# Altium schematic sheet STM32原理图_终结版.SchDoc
size 762 x 508 mm; SheetNumber: 0; SheetTotal: 0
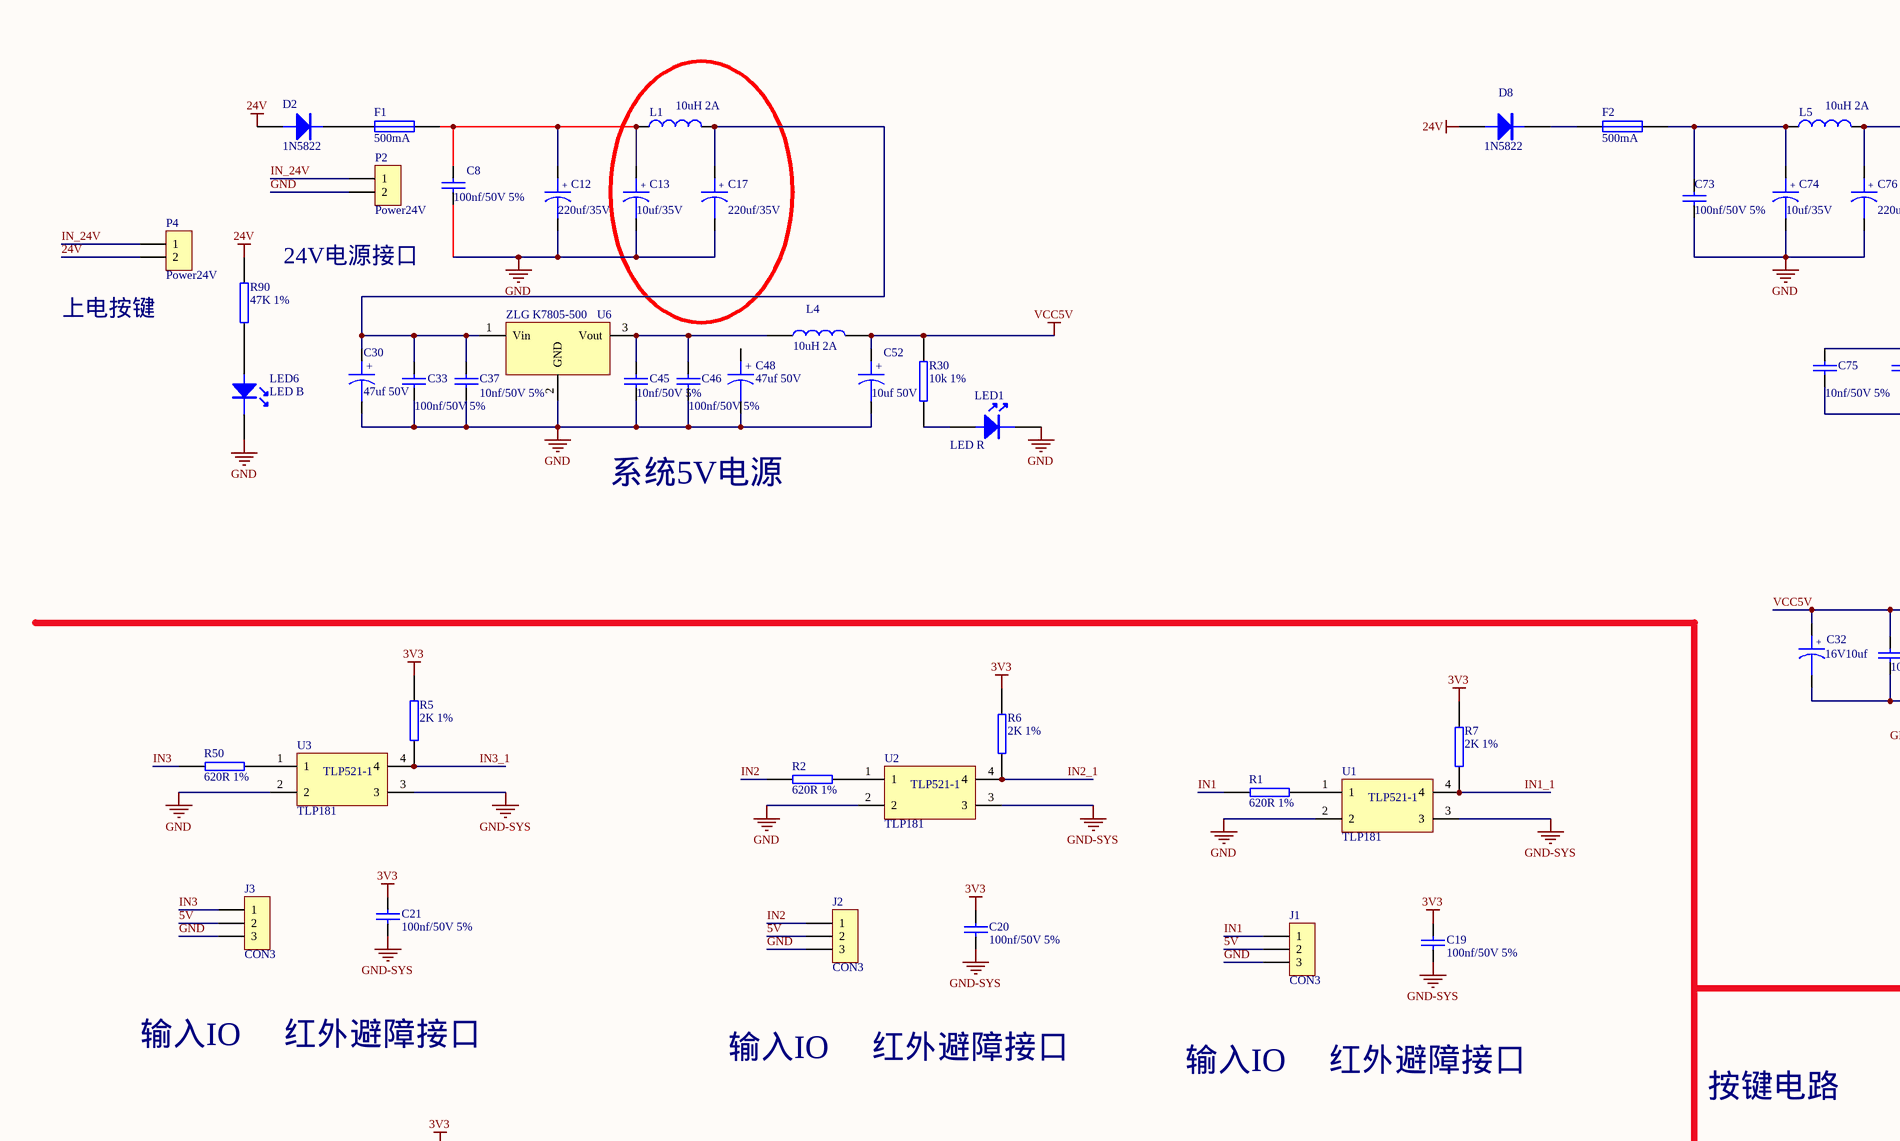
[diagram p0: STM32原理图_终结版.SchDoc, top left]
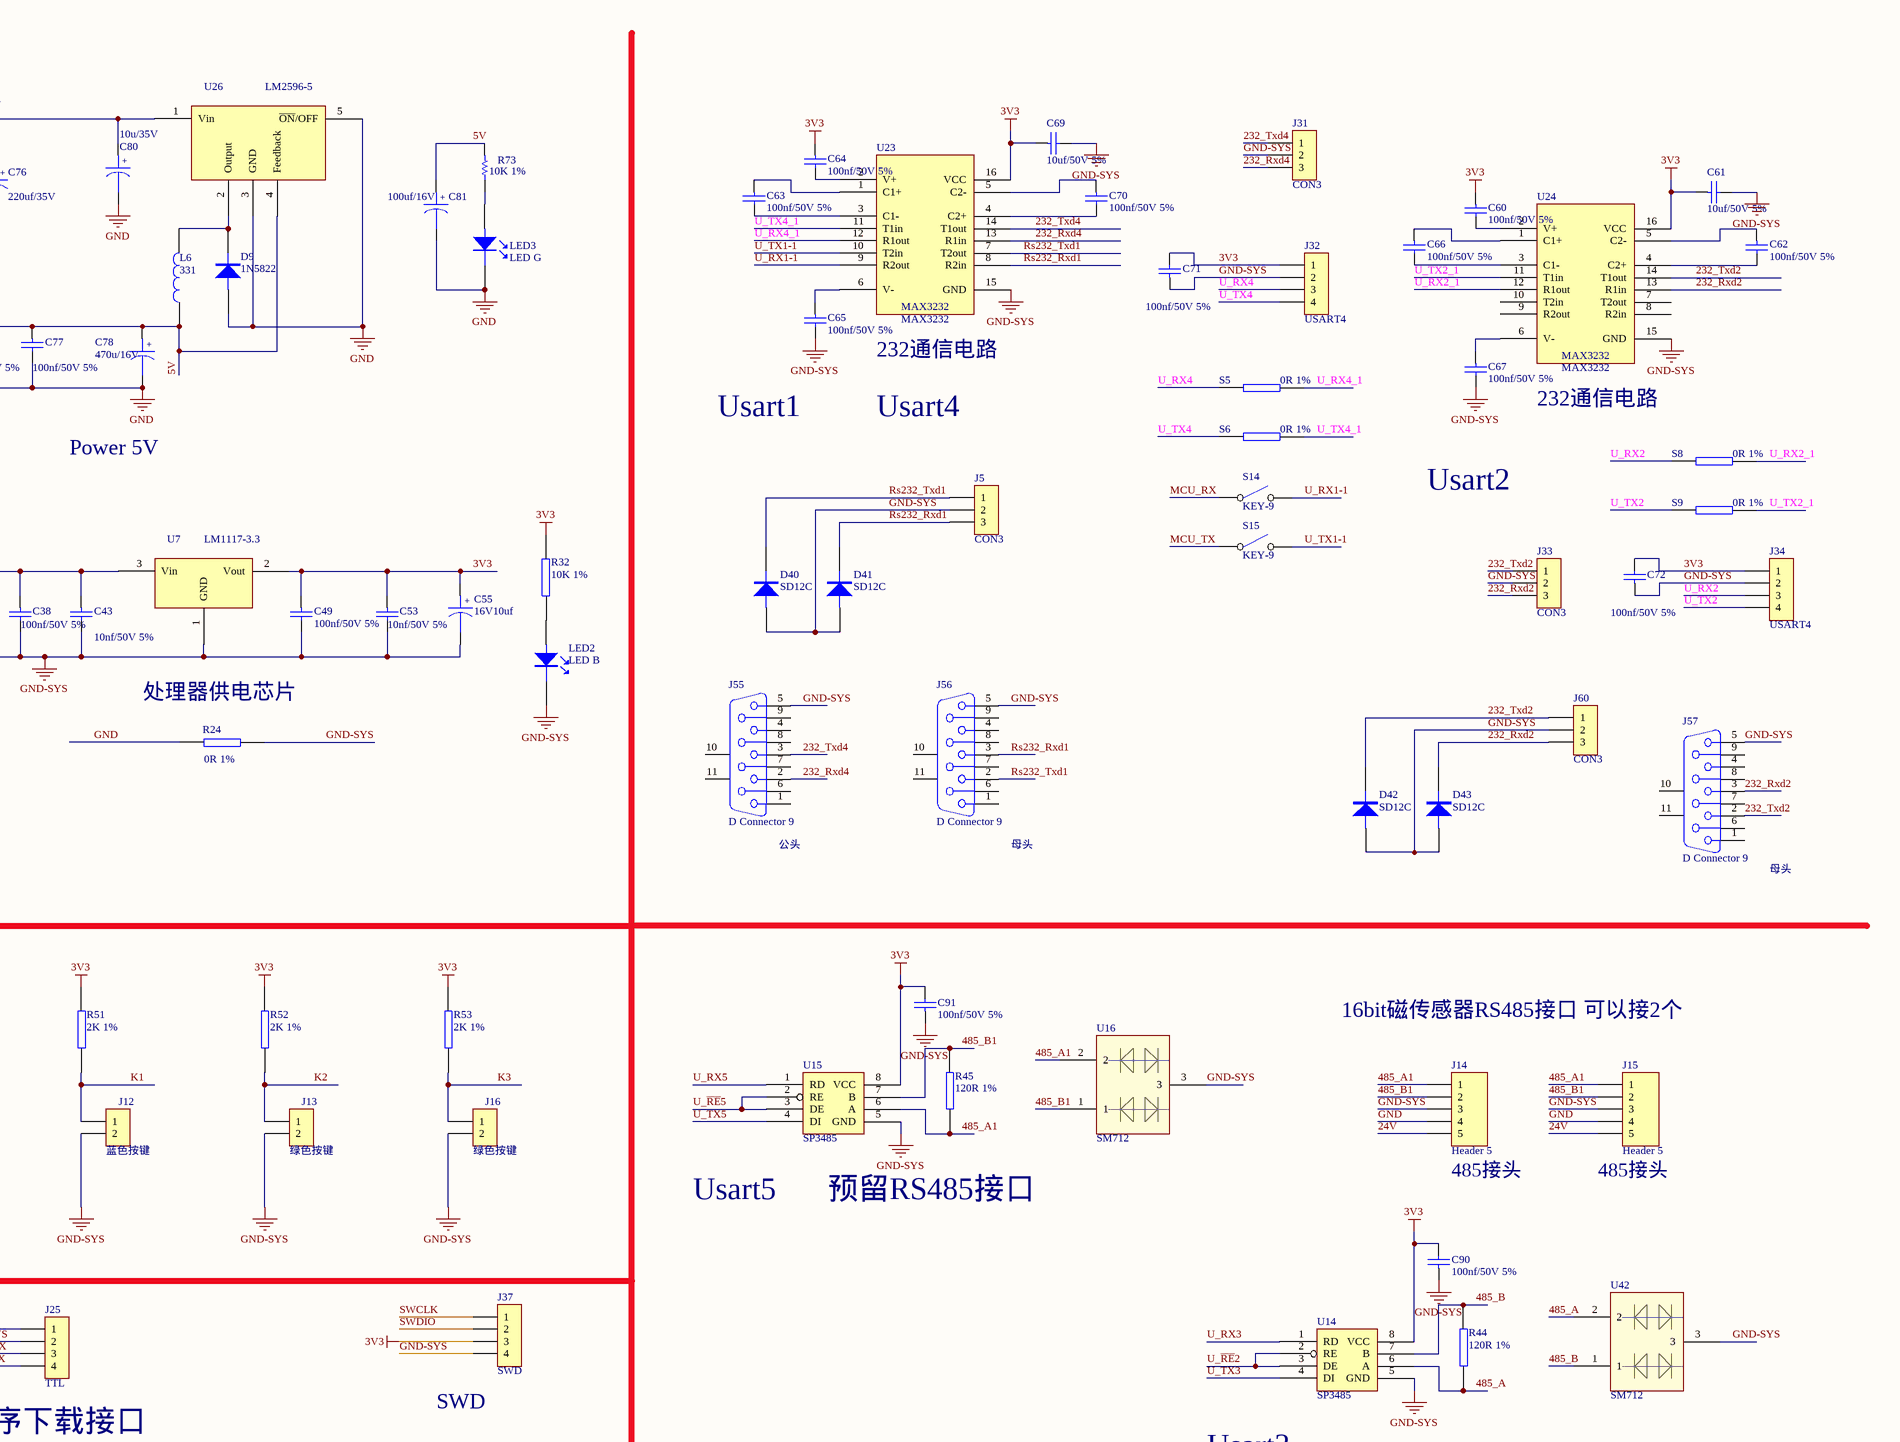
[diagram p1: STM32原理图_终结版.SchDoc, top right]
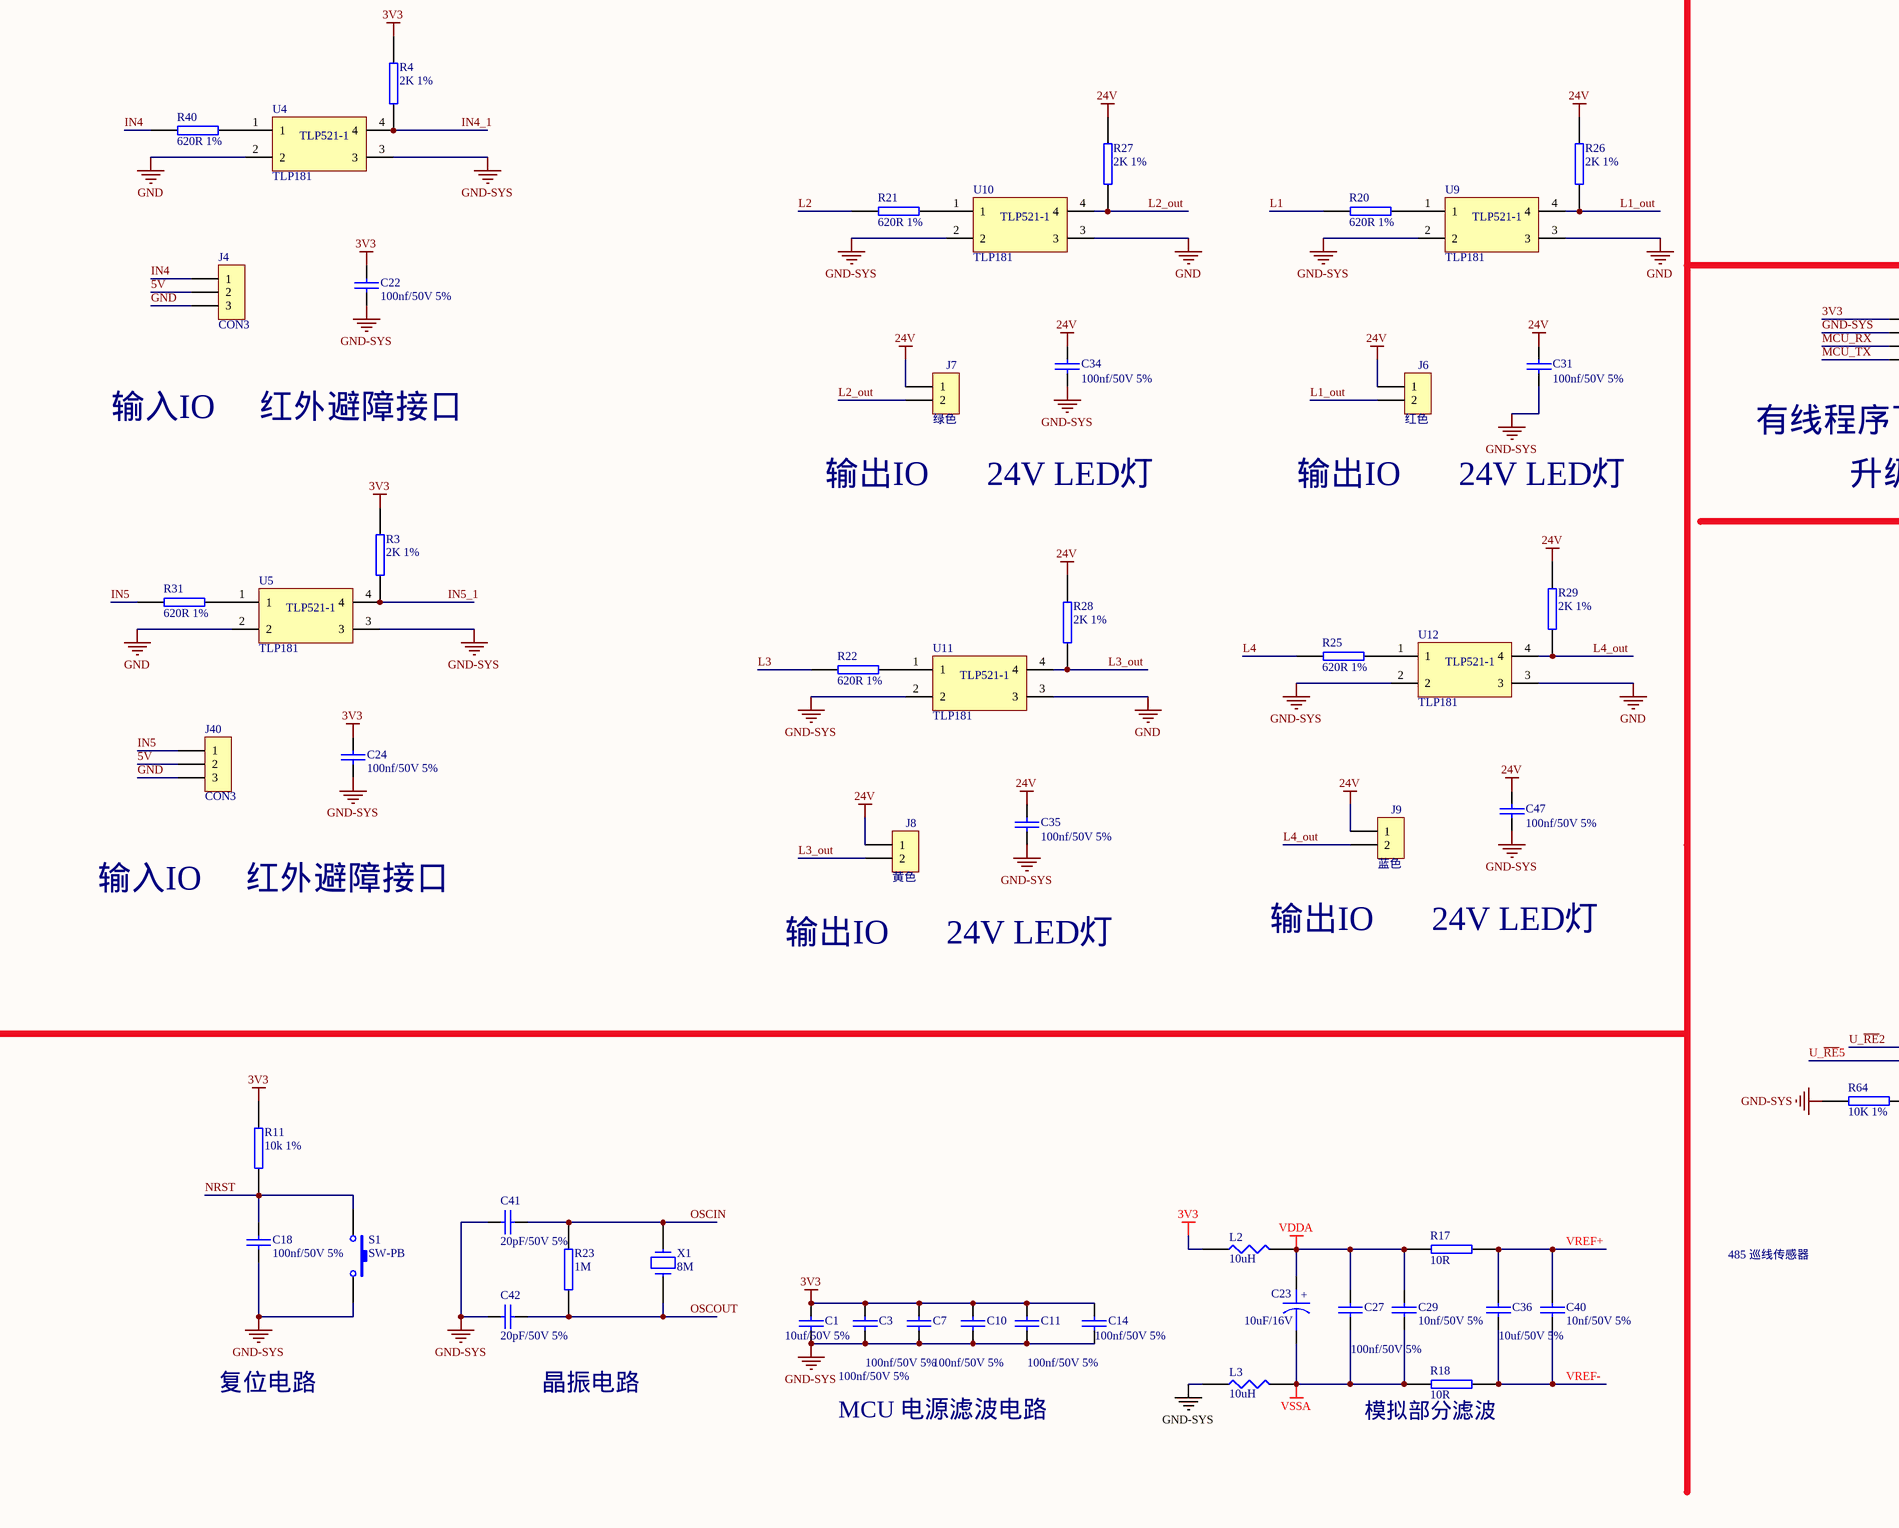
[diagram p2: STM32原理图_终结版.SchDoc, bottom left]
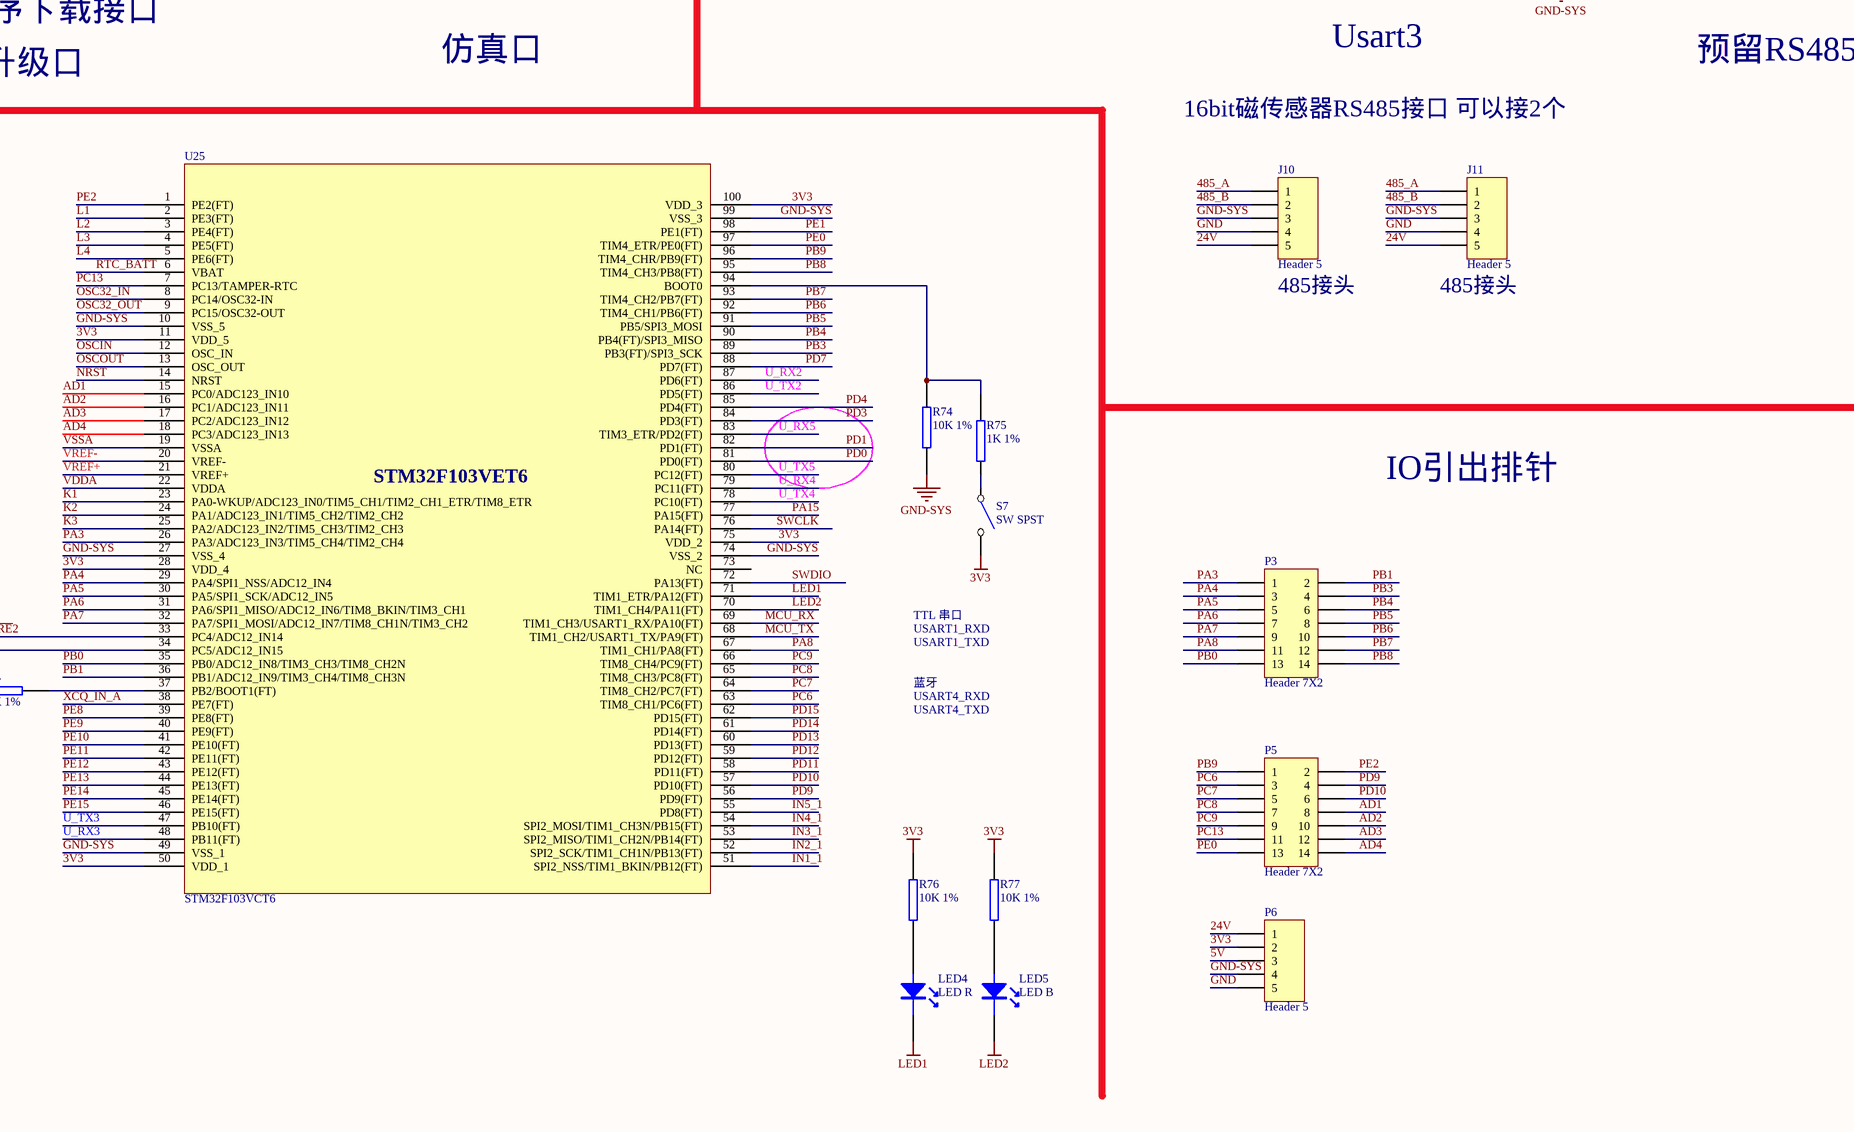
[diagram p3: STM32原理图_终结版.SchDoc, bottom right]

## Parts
C1  10uf/50V 5%  [0603]
C3  100nf/50V 5%  [0603]
C7  100nf/50V 5%  [0805C]
C8  100nf/50V 5%  [0805C]
C10  100nf/50V 5%  [0805C]
C11  100nf/50V 5%  [0805C]
C12  220uf/35V  [C10-35V330uf]
C13  10uf/35V  [C6.5-35V47uf]
C14  100nf/50V 5%  [0805C]
C17  220uf/35V  [C6.5-35V47uf]
C18  100nf/50V 5%  [0805C]
C19  100nf/50V 5%  [0805C]
C20  100nf/50V 5%  [0805C]
C21  100nf/50V 5%  [0805C]
C22  100nf/50V 5%  [0805C]
C23  10uF/16V  [0805C]
C24  100nf/50V 5%  [0805C]
C27  100nf/50V 5%  [0805C]
C29  10nf/50V 5%  [0805C]
C30  47uf 50V  [C6.5-35V47uf]
C31  100nf/50V 5%  [0805C]
C32  16V10uf  [1206-2]
C33  100nf/50V 5%  [0805C]
C34  100nf/50V 5%  [0805C]
C35  100nf/50V 5%  [0805C]
C36  10uf/50V 5%  [0805C]
C37  10nf/50V 5%  [0805C]
C38  100nf/50V 5%  [0805C]
C40  10nf/50V 5%  [0805C]
C41  20pF/50V 5%  [0805C]
C42  20pF/50V 5%  [0805C]
C43  10nf/50V 5%  [0805C]
C45  10nf/50V 5%  [0805C]
C46  100nf/50V 5%  [0805C]
C47  100nf/50V 5%  [0805C]
C48  47uf 50V  [C6.5-35V47uf]
C49  100nf/50V 5%  [0805C]
C52  10uf 50V  [C6.5-35V47uf]
C53  10nf/50V 5%  [0805C]
C55  16V10uf  [1206-2]
C60  100nf/50V 5%  [0805C]
C61  10uf/50V 5%  [0805C]
C62  100nf/50V 5%  [0805C]
C63  100nf/50V 5%  [0805C]
C64  100nf/50V 5%  [0805C]
C65  100nf/50V 5%  [0805C]
C66  100nf/50V 5%  [0805C]
C67  100nf/50V 5%  [0805C]
C69  10uf/50V 5%  [0805C]
C70  100nf/50V 5%  [0805C]
C71  100nf/50V 5%  [0805C]
C72  100nf/50V 5%  [0805C]
C73  100nf/50V 5%  [0805C]
C74  10uf/35V  [C6.5-35V47uf]
C75  10nf/50V 5%  [0805C]
C76  220uf/35V  [C6.5-35V47uf]
C77  100nf/50V 5%  [0805C]
C78  470u/16V  [C10-35V330uf]
C80  10u/35V  [C6.5-35V47uf]
C81  100uf/16V  [C6.5-35V47uf]
C90  100nf/50V 5%  [0805C]
C91  100nf/50V 5%  [0805C]
D2  1N5822  [SS34]
D8  1N5822  [SS34]
D9  1N5822  [SS34]
D40  SD12C  [SD12C]
D41  SD12C  [SD12C]
D42  SD12C  [SD12C]
D43  SD12C  [SD12C]
F1  500mA  [1812]
F2  500mA  [1812]
J1  CON3  [CON-3P-3.81]
J2  CON3  [CON-3P-3.81]
J3  CON3  [CON-3P-3.81]
J4  CON3  [CON-3P-3.81]
J5  CON3  [CON-3P-3.81]
J6  红色  [CON-2P-3.81]
J7  绿色  [CON-2P-3.81]
J8  黄色  [CON-2P-3.81]
J9  蓝色  [CON-2P-3.81]
J10  Header 5  [CON-5P-3.81]
J11  Header 5  [CON-5P-3.81]
J12  蓝色按键  [CON-2P-3.81]
J13  绿色按键  [CON-2P-3.81]
J14  Header 5  [CON-5P-3.81]
J15  Header 5  [CON-5P-3.81]
J16  绿色按键  [CON-2P-3.81]
J25  TTL  [SIP4]
J31  CON3  [CON-3P-3.81]
J32  USART4  [SIP4]
J33  CON3  [CON-3P-3.81]
J34  USART4  [SIP4]
J37  SWD  [SIP4]
J40  CON3  [CON-3P-3.81]
J55  D Connector 9  [DSUB1.385-2H9]
J56  D Connector 9  [DSUB1.385-2H9]
J57  D Connector 9  [DSUB1.385-2H9]
J60  CON3  [CON-3P-3.81]
L1  value 10uH 2A  [LC-8.2]  (hidden comment: Inductor)
L2  10uH  [0805]
L3  10uH  [0805]
L4  10uH 2A  [LC-8.2]
L5  value 10uH 2A  [LC-8.2]  (hidden comment: Inductor)
L6  331  [LC-10]
LED1  LED R  [0805D]
LED2  LED B  [0805D]
LED3  LED G  [0805D]
LED4  LED R  [0805D]
LED5  LED B  [0805D]
LED6  LED B  [0805D]
P2  Power24V  [CON-2P-3.81]
P3  Header 7X2  [HDR2X7]
P4  Power24V  [CON-2P-3.81]
P5  Header 7X2  [HDR2X7]
P6  Header 5  [HDR1X5]
R1  620R 1%  [0805R]
R2  620R 1%  [0805R]
R3  2K 1%  [0805R]
R4  2K 1%  [0805R]
R5  2K 1%  [0805R]
R6  2K 1%  [0805R]
R7  2K 1%  [0805R]
R11  10k 1%  [0805R]
R17  10R  [0805R]
R18  10R  [0805R]
R20  620R 1%  [0805R]
R21  620R 1%  [0805R]
R22  620R 1%  [0805R]
R23  1M  [0805R]
R24  0R 1%  [0805R]
R25  620R 1%  [0805R]
R26  2K 1%  [0805R]
R27  2K 1%  [0805R]
R28  2K 1%  [0805R]
R29  2K 1%  [0805R]
R30  10k 1%  [0805R]
R31  620R 1%  [0805R]
R32  10K 1%  [0805R]
R40  620R 1%  [0805R]
R44  120R 1%  [0805R]
R45  120R 1%  [0805R]
R50  620R 1%  [0805R]
R51  2K 1%  [0805R]
R52  2K 1%  [0805R]
R53  2K 1%  [0805R]
R64  10K 1%  [0805R]
R73  10K 1%  [0805R]
R74  10K 1%  [0805R]
R75  1K 1%  [0805R]
R76  10K 1%  [0805R]
R77  10K 1%  [0805R]
R90  47K 1%  [0805R]
S1  SW-PB  [DPST-4]
S5  0R 1%  [0805R]
S6  0R 1%  [0805R]
S7  SW SPST  [SIP2]
S8  0R 1%  [0805R]
S9  0R 1%  [0805R]
S14  KEY-9  [SIP2]
S15  KEY-9  [SIP2]
U1  TLP181  [TLP-181]
U2  TLP181  [TLP-181]
U3  TLP181  [TLP-181]
U4  TLP181  [TLP-181]
U5  TLP181  [TLP-181]
U6  ZLG K7805-500  [TO-220]
U7  LM1117-3.3  [SOT-223]
U9  TLP181  [TLP-181]
U10  TLP181  [TLP-181]
U11  TLP181  [TLP-181]
U12  TLP181  [TLP-181]
U14  SP3485  [SO-8]
U15  SP3485  [SO-8]
U16  SM712  [SM712]
U23  MAX3232  [SO-16]
U24  MAX3232  [SO-16]
U25  STM32F103VCT6  [LQFP100]
U26  LM2596-5  [TO-263-5]
U42  SM712  [SM712]
X1  8M  [CRYSTAL-T]

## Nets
3V3: C1.1 C3.1 C7.1 C10.1 C11.1 C14.1 C19.2 C20.2 C21.2 C22.2 C24.2 C49.1 C53.1 C55.1 C60.1 C61.1 C64.1 C69.1 C71.2 C72.2 C90.2 C91.2 J25.1 J32.1 J34.1 J37.3 L2.1 P6.2 R3.2 R4.2 R5.2 R6.2 R7.2 R11.2 R32.2 R51.1 R52.1 R53.1 R76.2 R77.2 S7.2(NO) U7.2(Vout) U14.8(VCC) U15.8(VCC) U23.16(VCC) U24.16(VCC) U25.11(VDD_5) U25.28(VDD_4) U25.50(VDD_1) U25.75(VDD_2) U25.100(VDD_3)
24V: C31.2 C34.2 C35.2 C47.2 D2.1(A) D8.1(A) J6.1 J7.1 J8.1 J9.1 J10.5 J11.5 J14.5 J15.5 P4.2 P6.1 R26.1 R27.1 R28.1 R29.1 R90.2
GND: C8.2 C12.2 C13.2 C17.2 C30.2 C33.2 C37.2 C45.2 C46.2 C48.2 C52.2 C73.2 C74.2 C75.2 C76.2 C77.2 C78.2 C80.2 C81.2 D9.1(A) J1.3 J2.3 J3.3 J4.3 J10.4 J11.4 J14.4 J15.4 J40.3 LED1.2 LED3.2 LED6.2 P2.2 P6.5 R24.1 U1.2 U2.2 U3.2 U4.2 U5.2 U6.2(GND) U9.3 U10.3 U11.3 U12.3 U26.3(GND) U26.5(~{ON}/OFF)
GND-SYS: C1.2 C3.2 C7.2 C10.2 C11.2 C14.2 C18.1 C19.1 C20.1 C21.1 C22.1 C24.1 C31.1 C32.2 C34.1 C35.1 C38.2 C41.1 C42.1 C43.2 C47.1 C49.2 C53.2 C55.2 C61.2 C65.2 C67.2 C69.2 C71.1 C72.1 C90.1 C91.1 D40.1(A) D41.1(A) D42.1(A) D43.1(A) J5.2 J10.3 J11.3 J12.2 J13.2 J14.3 J15.3 J16.2 J25.2 J31.2 J32.2 J33.2 J34.2 J37.4 J55.5 J56.5 J57.5 J60.2 L3.1 LED2.2 P6.4 R24.2 R64.1 R74.2 S1.2 U1.3 U2.3 U3.3 U4.3 U5.3 U7.1(GND) U9.2 U10.2 U11.2 U12.2 U14.5(GND) U15.5(GND) U16.3 U23.15(GND) U24.15(GND) U25.10(VSS_5) U25.27(VSS_4) U25.49(VSS_1) U25.74(VSS_2) U25.99(VSS_3) U42.3
LED1: LED4.2 U25.71(TIM1_ETR/PA12(FT))
LED2: LED5.2 U25.70(TIM1_CH4/PA11(FT))
VCC5V: C32.1 C38.1 C43.1 C52.1 L4.2 R30.2 U7.3(Vin)
VDDA: C23.1 C27.2 C29.2 L2.2 R17.2 U25.22(VDDA)
VSSA: C23.2 C27.1 C29.1 L3.2 R18.2 U25.19(VSSA)
5V: C75.1 C77.1 C78.1 C81.1 J1.2 J2.2 J3.2 J4.2 J40.2 L6.1 P6.3 R73.2 U26.4(Feedback)
232_Rxd2: D43.2(K) J33.3 J57.3 J60.3 U24.13(R1in)
232_Rxd4: J31.3 J55.2 U23.13(R1in)
232_Txd2: D42.2(K) J33.1 J57.2 J60.1 U24.14(T1out)
232_Txd4: J31.1 J55.3 U23.14(T1out)
485_A: J10.1 J11.1 R44.2 U14.6(A) U42.2
485_A1: J14.1 J15.1 R45.2 U15.6(A) U16.2
485_B: J10.2 J11.2 R44.1 U14.7(B) U42.1
485_B1: J14.2 J15.2 R45.1 U15.7(B) U16.1
AD1: P5.8 U25.15(PC0/ADC123_IN10)
AD2: P5.10 U25.16(PC1/ADC123_IN11)
AD3: P5.12 U25.17(PC2/ADC123_IN12)
AD4: P5.14 U25.18(PC3/ADC123_IN13)
IN1: J1.1 R1.2
IN1_1: R7.1 U1.4 U25.51(SPI2_NSS/TIM1_BKIN/PB12(FT))
IN2: J2.1 R2.2
IN2_1: R6.1 U2.4 U25.52(SPI2_SCK/TIM1_CH1N/PB13(FT))
IN3: J3.1 R50.2
IN3_1: R5.1 U3.4 U25.53(SPI2_MISO/TIM1_CH2N/PB14(FT))
IN4: J4.1 R40.2
IN4_1: R4.1 U4.4 U25.54(SPI2_MOSI/TIM1_CH3N/PB15(FT))
IN5: J40.1 R31.2
IN5_1: R3.1 U5.4 U25.55(PD8(FT))
IN_24V: P2.1 P4.1
K1: J12.1 R51.2 U25.23(PA0-WKUP/ADC123_IN0/TIM5_CH1/TIM2_CH1_ETR/TIM8_ETR)
K2: J13.1 R52.2 U25.24(PA1/ADC123_IN1/TIM5_CH2/TIM2_CH2)
K3: J16.1 R53.2 U25.25(PA2/ADC123_IN2/TIM5_CH3/TIM2_CH3)
L1: R20.2 U25.2(PE3(FT))
L1_out: J6.2 R26.2 U9.4
L2: R21.2 U25.3(PE4(FT))
L2_out: J7.2 R27.2 U10.4
L3: R22.2 U25.4(PE5(FT))
L3_out: J8.2 R28.2 U11.4
L4: R25.2 U25.5(PE6(FT))
L4_out: J9.2 R29.2 U12.4
MCU_RX: J25.3 S14.1(COMMON) U25.69(TIM1_CH3/USART1_RX/PA10(FT))
MCU_TX: J25.4 S15.1(COMMON) U25.68(TIM1_CH2/USART1_TX/PA9(FT))
NRST: C18.2 R11.1 S1.1 U25.14(NRST)
OSC32_IN: U25.8(PC14/OSC32-IN)
OSC32_OUT: U25.9(PC15/OSC32-OUT)
OSCIN: C41.2 R23.2 U25.12(OSC_IN) X1.2
OSCOUT: C42.2 R23.1 U25.13(OSC_OUT) X1.1
PA3: P3.1 U25.26(PA3/ADC123_IN3/TIM5_CH4/TIM2_CH4)
PA4: P3.3 U25.29(PA4/SPI1_NSS/ADC12_IN4)
PA5: P3.5 U25.30(PA5/SPI1_SCK/ADC12_IN5)
PA6: P3.7 U25.31(PA6/SPI1_MISO/ADC12_IN6/TIM8_BKIN/TIM3_CH1)
PA7: P3.9 U25.32(PA7/SPI1_MOSI/ADC12_IN7/TIM8_CH1N/TIM3_CH2)
PA8: P3.11 U25.67(TIM1_CH1/PA8(FT))
PA15: U25.77(PA15(FT))
PB0: P3.13 U25.35(PB0/ADC12_IN8/TIM3_CH3/TIM8_CH2N)
PB1: P3.2 U25.36(PB1/ADC12_IN9/TIM3_CH4/TIM8_CH3N)
PB3: P3.4 U25.89(PB3(FT)/SPI3_SCK)
PB4: P3.6 U25.90(PB4(FT)/SPI3_MISO)
PB5: P3.8 U25.91(PB5/SPI3_MOSI)
PB6: P3.10 U25.92(TIM4_CH1/PB6(FT))
PB7: P3.12 U25.93(TIM4_CH2/PB7(FT))
PB8: P3.14 U25.95(TIM4_CH3/PB8(FT))
PB9: P5.1 U25.96(TIM4_CHR/PB9(FT))
PC6: P5.3 U25.63(TIM8_CH1/PC6(FT))
PC7: P5.5 U25.64(TIM8_CH2/PC7(FT))
PC8: P5.7 U25.65(TIM8_CH3/PC8(FT))
PC9: P5.9 U25.66(TIM8_CH4/PC9(FT))
PC13: P5.11 U25.7(PC13/TAMPER-RTC)
PD0: U25.81(PD0(FT))
PD1: U25.82(PD1(FT))
PD3: U25.84(PD3(FT))
PD4: U25.85(PD4(FT))
PD7: U25.88(PD7(FT))
PD9: P5.4 U25.56(PD9(FT))
PD10: P5.6 U25.57(PD10(FT))
PD11: U25.58(PD11(FT))
PD12: U25.59(PD12(FT))
PD13: U25.60(PD13(FT))
PD14: U25.61(PD14(FT))
PD15: U25.62(PD15(FT))
PE0: P5.13 U25.97(TIM4_ETR/PE0(FT))
PE1: U25.98(PE1(FT))
PE2: P5.2 U25.1(PE2(FT))
PE8: U25.39(PE8(FT))
PE9: U25.40(PE9(FT))
PE10: U25.41(PE10(FT))
PE11: U25.42(PE11(FT))
PE12: U25.43(PE12(FT))
PE13: U25.44(PE13(FT))
PE14: U25.45(PE14(FT))
PE15: U25.46(PE15(FT))
Rs232_Rxd1: D41.2(K) J5.3 J56.3 U23.8(R2in)
Rs232_Txd1: D40.2(K) J5.1 J56.2 U23.7(T2out)
RTC_BATT: U25.6(VBAT)
SWCLK: J37.1 U25.76(PA14(FT))
SWDIO: J37.2 U25.72(PA13(FT))
U_~{RE}2: U14.2(RE) U14.3(DE) U25.33(PC4/ADC12_IN14)
U_~{RE}5: U15.2(RE) U15.3(DE) U25.34(PC5/ADC12_IN15)
U_RX1-1: S14.2(NO) U23.9(R2out)
U_RX2: J34.3 S8.1 U25.87(PD6(FT))
U_RX2_1: S8.2 U24.12(R1out)
U_RX3: U14.1(RD) U25.48(PB11(FT))
U_RX4: J32.3 S5.1 U25.79(PC11(FT))
U_RX4_1: S5.2 U23.12(R1out)
U_RX5: U15.1(RD) U25.83(TIM3_ETR/PD2(FT))
U_TX1-1: S15.2(NO) U23.10(T2in)
U_TX2: J34.4 S9.1 U25.86(PD5(FT))
U_TX2_1: S9.2 U24.11(T1in)
U_TX3: U14.4(DI) U25.47(PB10(FT))
U_TX4: J32.4 S6.1 U25.78(PC10(FT))
U_TX4_1: S6.2 U23.11(T1in)
U_TX5: U15.4(DI) U25.80(PC12(FT))
VREF+: C36.2 C40.2 R17.1 U25.21(VREF+)
VREF-: C36.1 C40.1 R18.1 U25.20(VREF-)
XCQ_IN_A: U25.38(PE7(FT))
NetC8_1: C8.1 C12.1 C13.1 F1.2 L1.1
NetC17_1: C17.1 C30.1 C33.1 C37.1 L1.2 U6.1(Vin)
NetC45_1: C45.1 C46.1 L4.1 U6.3(Vout)
NetC60_2: C60.2 U24.2(V+)
NetC62_1: C62.1 U24.5(C2-)
NetC62_2: C62.2 U24.4(C2+)
NetC63_1: C63.1 U23.1(C1+)
NetC63_2: C63.2 U23.3(C1-)
NetC64_2: C64.2 U23.2(V+)
NetC65_1: C65.1 U23.6(V-)
NetC66_1: C66.1 U24.1(C1+)
NetC66_2: C66.2 U24.3(C1-)
NetC67_1: C67.1 U24.6(V-)
NetC70_1: C70.1 U23.5(C2-)
NetC70_2: C70.2 U23.4(C2+)
NetC73_1: C73.1 C74.1 F2.2 L5.1
NetC76_1: C76.1 C80.1 L5.2 U26.1(Vin)
NetD2_2: D2.2(K) F1.1
NetD8_2: D8.2(K) F2.1
NetD9_2: D9.2(K) L6.2 U26.2(Output)
NetLED1_1: LED1.1 R30.1
NetLED2_1: LED2.1 R32.1
NetLED3_1: LED3.1 R73.1
NetLED4_1: LED4.1 R76.1
NetLED5_1: LED5.1 R77.1
NetLED6_1: LED6.1 R90.1
NetR1_1: R1.1 U1.1
NetR2_1: R2.1 U2.1
NetR20_1: R20.1 U9.1
NetR21_1: R21.1 U10.1
NetR22_1: R22.1 U11.1
NetR25_1: R25.1 U12.1
NetR31_1: R31.1 U5.1
NetR40_1: R40.1 U4.1
NetR50_1: R50.1 U3.1
NetR64_2: R64.2 U25.37(PB2/BOOT1(FT))
NetR74_1: R74.1 R75.1 U25.94(BOOT0)
NetR75_2: R75.2 S7.1(COMMON)

Not connected (* = marked no-connect by the designer): C48 1; J55 1 4 6 7 8 9 10(MH1) 11(MH2); J56 1 4 6 7 8 9 10(MH1) 11(MH2); J57 1 4 6 7 8 9 10(MH1) 11(MH2); U24 7(T2out) 8(R2in) 9(R2out) 10(T2in); U25 73(NC)

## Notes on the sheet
- 24V电源接口
- 上电按键
- 232通信电路
- Usart1
- Usart4
- 系统5V电源
- Power 5V
- Usart2
- (near R24) 处理器供电芯片
- (near J55) 公头
- 母头
- 输入IO
- 红外避障接口
- 按键电路
- 16bit磁传感器RS485接口 可以接2个
- Usart5
- 预留RS485接口
- (near J14) 485接头
- (near J15) 485接头
- (near J37) SWD
- (near J25) 有线程序下载接口
- 仿真口
- Usart3
- 输出IO
- 24V LED灯
- 升级口
- (near J10) 485接头
- (near J11) 485接头
- IO引出排针
- TTL 串口
- USART1_RXD
- USART1_TXD
- 蓝牙
- USART4_RXD
- USART4_TXD
- 485 巡线传感器
- 复位电路
- 晶振电路
- MCU 电源滤波电路
- (near R18) 模拟部分滤波

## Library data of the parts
C1 C3 C7 C8 C10 C11 C14 C18-C22 C24 C27 C29 C31 C33-C38 C40-C43 C45-C47 C49 C53 C60-C67 C69-C73 C75 C77 C90 C91 = CAP: Capacitor
C12 C13 C17 C23 C30 C48 C52 C74 C76 C78 C80 C81 = CAPACITOR POL: Capacitor
C32 C55 = CAP+
D2 D8 D9 D40-D43 = DIODE
F1 F2 = Fuse 1: Fuse
J1-J5 J31 J33 J40 J60 = CON3: Connector
J6-J9 J12 J13 J16 P2 P4 = CON2: Connector
J10 J11 J14 J15 P6 = Header 5: Header, 5-Pin
J25 J32 J34 = CON4: Connector
J37 = CON4: 5264,, 4-Pin
J55-J57 = D Connector 9: Receptacle Assembly, 9 Position, Right Angle; PackageDocument: O; Positions: 9
L1 L5 = Inductor: Code_IEC: 1005
L2 L3 = RES1
L4 = INDUCTOR1
L6 = INDUCTOR
LED1-LED6 = LED
P3 P5 = Header 7X2: Header, 7-Pin, Dual row
R1-R7 R11 R17 R18 R20-R32 R40 R44 R45 R50-R53 R64 R74-R77 R90 = RES2
R73 = Res1: Resistor
S1 = SW-PB: Switch
S5 S6 S8 S9 = RES
S14 S15 = KEY-2
U1-U5 U9-U12 = TLP521-1
U6 = VOLTREG
U7 = LM1117
U14 U15 = MAX485
U26 = LM2596-5.0
X1 = CRYSTAL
